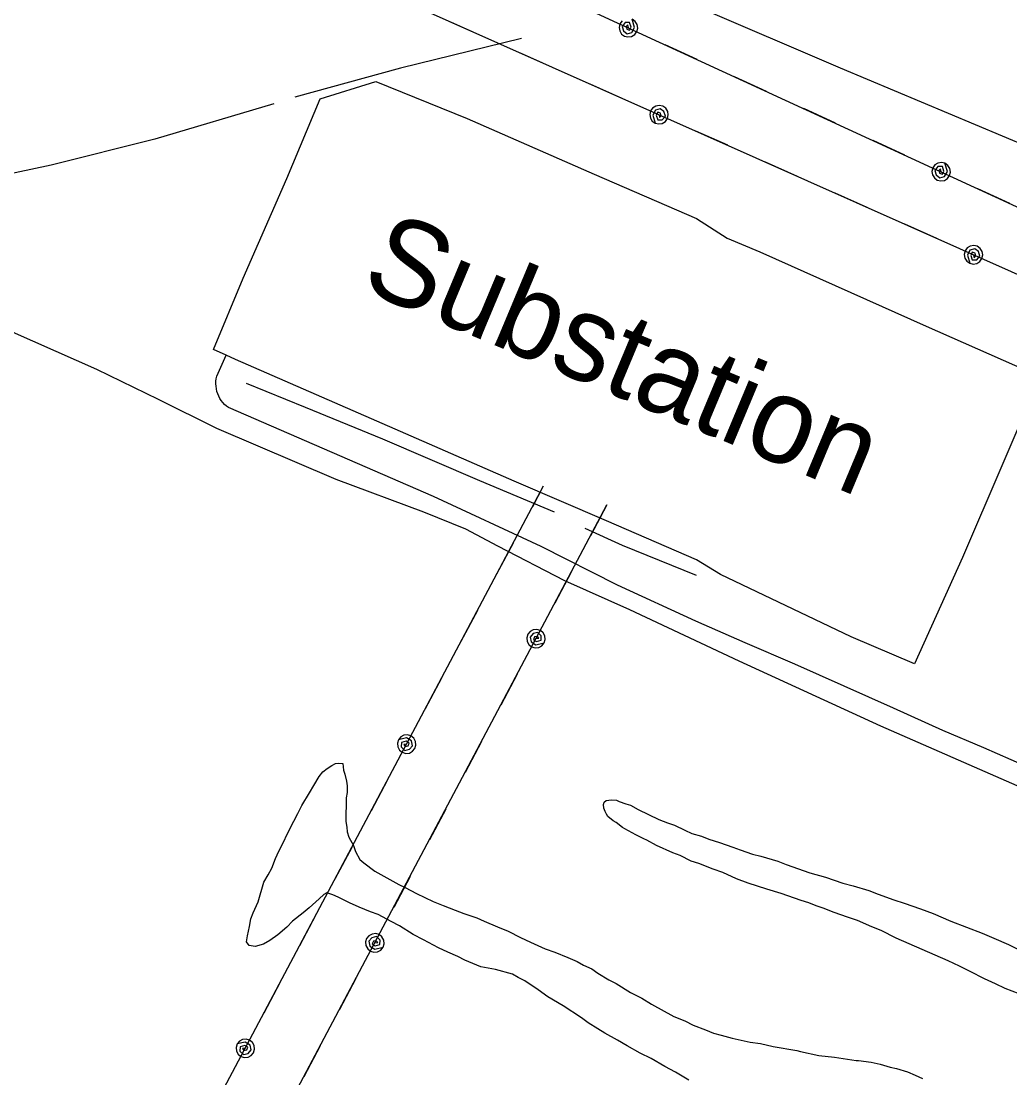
# Model space of a CAD drawing. Extents: x 3297735 to 3335592, y 670436 to 695807.
# Drawn here: x 3305005 to 3305964, y 683651 to 684677 of the extents above; entities that cross this region are included whole.
import ezdxf

# ---------------------------------------------------------------- set-up
doc = ezdxf.new("R2010")
doc.units = 0
for name, color, linetype in [('V-ROAD-CNTR', 7, 'Continuous'), ('V-SITE-OTLN', 7, 'Continuous'), ('V-SITE-OTLN-IDEN', 7, 'Continuous'), ('V-SITE-VEGE', 7, 'Continuous'), ('V-TOPO-SHOR', 7, 'Continuous'), ('V-UTIL-LINE', 7, 'Continuous')]:
    doc.layers.add(name, color=color, linetype=linetype)

msp = doc.modelspace()

# ---------------------------------------------------------------- linework, layer by layer
at = {"layer": 'V-ROAD-CNTR'}
for points in [[(3305206.1, 684301.6), (3305204.1, 684303.1), (3305202.3, 684304.7), (3305200.7, 684306.6), (3305199.2, 684308.5), (3305197.8, 684310.6), (3305196.7, 684312.8), (3305195.7, 684315.1), (3305195, 684317.4), (3305194.4, 684319.8), (3305194.1, 684322.3), (3305193.9, 684324.7), (3305194, 684327.2), (3305194.3, 684329.7), (3305194.8, 684332.1), (3305203.8, 684352.5)], [(3305659.4, 684094.3), (3305583.4, 684129.5), (3305509.6, 684166.8), (3305405, 684215.4), (3305306.6, 684258.2), (3305206.1, 684301.6)], [(3305978.8, 683954.1), (3305939, 683971.4), (3305899.1, 683988.5), (3305851.4, 684010.1), (3305803.5, 684031.4), (3305755.6, 684052.6), (3305707.5, 684073.5), (3305659.4, 684094.3)]]:
    msp.add_lwpolyline(points, dxfattribs=at)
at = {"layer": 'V-SITE-OTLN'}
msp.add_lwpolyline([(3305660.1, 684485), (3305689.9, 684465.9), (3305721.7, 684452.9), (3305883, 684380.7), (3305993.4, 684331.9), (3305918.2, 684156.1), (3305871.7, 684053.2), (3305810.1, 684079.3), (3305683.6, 684139.7), (3305660.1, 684153.9), (3305573, 684191.8), (3305483.3, 684230.4), (3305345, 684290.7), (3305212.9, 684348.4), (3305203.8, 684352.5), (3305191.6, 684358.1), (3305220.5, 684427.1), (3305262.9, 684523.9), (3305295, 684601.2), (3305349.1, 684618), (3305437.7, 684582), (3305561, 684528.2)], close=True, dxfattribs=at)
at = {"layer": 'V-SITE-VEGE'}
for points in [[(3305652.6, 683649.2), (3305639.7, 683657), (3305629.5, 683662.5), (3305616.1, 683670.3), (3305605.4, 683675.4), (3305593, 683682.3), (3305583.6, 683687.8), (3305571.2, 683694.7), (3305564.5, 683698.8), (3305555.1, 683704.7), (3305548.5, 683709.7), (3305530.7, 683721.2), (3305516, 683729.9), (3305506.7, 683736.7), (3305493.8, 683745.4), (3305487.1, 683748.7), (3305481.8, 683751.9), (3305465.2, 683756.6), (3305450.9, 683759), (3305435.3, 683765.5), (3305428.6, 683769.1), (3305418.8, 683773.3), (3305409.9, 683777.5), (3305395.2, 683785.3), (3305385.4, 683790.3), (3305372.1, 683799), (3305364.1, 683803.2), (3305351.2, 683810), (3305344, 683812.4), (3305332.9, 683817), (3305323.5, 683821.2), (3305312.4, 683826.7), (3305307.5, 683829), (3305301.7, 683830.9), (3305298.5, 683829.1), (3305294, 683825.1), (3305284.4, 683816.3), (3305278.6, 683811.4), (3305268.1, 683803.5), (3305262.7, 683797.7), (3305254.1, 683790.2), (3305246.4, 683784.5), (3305240.1, 683781), (3305232, 683778.9), (3305226.1, 683779.8), (3305223.5, 683783.5), (3305224.5, 683789.3), (3305226.4, 683798.2), (3305227.8, 683805.8), (3305230.1, 683811.6), (3305234.8, 683822.3), (3305240.4, 683841.1), (3305244.5, 683848.2), (3305248.2, 683854.9), (3305251.9, 683864.2), (3305255.1, 683871.4), (3305259.7, 683880.7), (3305262.9, 683887), (3305269.4, 683900.3), (3305273.5, 683907.9), (3305277.2, 683915.5), (3305284.6, 683927.9), (3305289.1, 683935), (3305294.2, 683943.9), (3305297.8, 683948.4), (3305301.9, 683951.5), (3305306.4, 683954.5), (3305310, 683956.3), (3305313.2, 683956.7), (3305317.2, 683956.2), (3305317.6, 683949.9), (3305318.9, 683945.9), (3305320.6, 683939.1), (3305321.4, 683934.6), (3305321.3, 683928.3), (3305320.4, 683923)], [(3305320.4, 683923), (3305320.1, 683900.1), (3305320.9, 683894.7), (3305321.3, 683890.2), (3305323, 683884.8), (3305327.4, 683876.7), (3305329.5, 683870.9), (3305333.5, 683863.2), (3305337.5, 683860), (3305348.1, 683851.8), (3305357, 683847.2), (3305371.3, 683838.9), (3305377.5, 683836.2), (3305388.6, 683830.2), (3305396.7, 683826.5), (3305404.7, 683822.4), (3305414.5, 683818.6), (3305426.1, 683814), (3305434.6, 683810.8), (3305447.1, 683806.6), (3305454.2, 683803.3), (3305467.1, 683797.8), (3305477.4, 683793.6), (3305489.4, 683787.6), (3305499.2, 683783), (3305513.5, 683776.6), (3305522.9, 683773.3), (3305535.3, 683768.2), (3305544.3, 683764.1), (3305550.5, 683760.8), (3305558.5, 683757.1), (3305564.3, 683753), (3305575, 683746.6), (3305582.1, 683742.9), (3305596.3, 683734.2), (3305607, 683728.7), (3305616.4, 683722.8), (3305638.2, 683710.8), (3305648.9, 683706.7), (3305656.9, 683702.5), (3305668.9, 683697.9), (3305676.5, 683694.6), (3305684.1, 683692.7), (3305694.8, 683689.9), (3305712.3, 683686.1), (3305722.1, 683684.6), (3305734.6, 683681.8), (3305757.4, 683677.9), (3305761, 683676.9), (3305778.9, 683673.1), (3305794.1, 683671.6), (3305815.2, 683668.2), (3305817.4, 683668.1), (3305829.5, 683666.6), (3305838.4, 683664.7), (3305848.2, 683661.9), (3305854.1, 683660.5), (3305864.8, 683657.2), (3305872.4, 683654), (3305879.5, 683650.8)], [(3305986.7, 683727.8), (3305959.5, 683738), (3305950.2, 683742.6), (3305939.5, 683747.3), (3305925.7, 683754.6), (3305915.4, 683759.7), (3305904.3, 683764.8), (3305853.9, 683786.9), (3305839.2, 683794.3), (3305830.3, 683798), (3305816.5, 683804), (3305806.6, 683807.3), (3305793.7, 683811.9), (3305783, 683816.1), (3305776.3, 683818.4), (3305769.2, 683821.2), (3305761.6, 683823.6), (3305742.4, 683830.1), (3305728.5, 683834.3), (3305710.2, 683840.4), (3305699.1, 683844.5), (3305685.7, 683850.5), (3305676.3, 683853.8), (3305662.5, 683859.4), (3305654.9, 683861.7), (3305644.2, 683867.2), (3305637.1, 683869.6), (3305621.5, 683876.9), (3305612.1, 683882), (3305609, 683883.4), (3305601.4, 683887.1), (3305590.8, 683893), (3305588.5, 683894.4), (3305582.3, 683899), (3305579.2, 683900.8), (3305574.3, 683904.9), (3305573, 683907.1), (3305571.7, 683909.9), (3305570.4, 683913), (3305570, 683916.6), (3305570.5, 683918.8), (3305572.7, 683920.6), (3305577.7, 683921), (3305582.6, 683920.9), (3305585.3, 683919.5), (3305591.5, 683917.2), (3305596, 683915.8), (3305603.6, 683911.7), (3305623.6, 683902), (3305632.1, 683898.8), (3305638.8, 683896.4), (3305649, 683891.8), (3305655.7, 683888.6), (3305665.1, 683885.8), (3305672.2, 683883), (3305682.5, 683879.7), (3305695.4, 683875.1), (3305702.6, 683872.7), (3305714.6, 683868.5), (3305722.7, 683866.6), (3305739.2, 683861.5), (3305747.2, 683858.3), (3305770, 683850.3), (3305785.2, 683846.1), (3305793.7, 683843.3), (3305802.1, 683840.1), (3305812, 683837.7)], [(3305812, 683837.7), (3305827.2, 683833), (3305836.5, 683829.7), (3305851.7, 683824.2), (3305861.5, 683820.9), (3305877.6, 683815.3), (3305889.6, 683810.7), (3305907, 683803.3), (3305937.4, 683791.7), (3305948.5, 683787), (3305962.8, 683780.6), (3305972.6, 683776)]]:
    msp.add_lwpolyline(points, dxfattribs=at)
at = {"layer": 'V-TOPO-SHOR'}
msp.add_line((3305839, 683992.6), (3305701.4, 684055.7), dxfattribs=at)
for points in [[(3306009.5, 684543), (3305799.7, 684631.1), (3305660.1, 684690.9)], [(3305490.4, 684659.8), (3305372.9, 684630.9), (3305270.4, 684602.9)], [(3305250.2, 684596.3), (3305134.8, 684562.1), (3305034, 684537), (3304909.2, 684510.2), (3304804.6, 684483.7), (3304809.3, 684485)], [(3305701.4, 684055.7), (3305595.4, 684105.3), (3305532.5, 684133.7), (3305467.6, 684167.2), (3305436.3, 684183.6), (3305395.5, 684200.1), (3305310.5, 684231.8), (3305194.8, 684281.3), (3305138.4, 684309.6), (3305078.5, 684338.7), (3304976.5, 684383.7), (3304916.4, 684409.8), (3304856.3, 684434.6), (3304791.3, 684460.1)], [(3305522.5, 684200.1), (3305450, 684230.5), (3305355.8, 684271), (3305280.8, 684301.8), (3305223.6, 684325.1)], [(3305660.1, 684138.6), (3305588.5, 684168), (3305552.1, 684184.5)], [(3306341.8, 683773), (3306260.6, 683808.1), (3306123.8, 683866.6), (3305971.4, 683934.6), (3305839, 683992.6)]]:
    msp.add_lwpolyline(points, dxfattribs=at)
at = {"layer": 'V-UTIL-LINE'}
for points in [[(3301855.9, 686290.9), (3302508.1, 686015.9), (3303718.5, 685476.3), (3304541.8, 685139.2), (3305359.1, 684778.4), (3306932, 684054.1), (3307415, 683680.5), (3308058.5, 683385.6), (3308857.4, 683018.6), (3310271.9, 682456)], [(3310256.8, 682384.2), (3308755.9, 682962.6), (3307386.3, 683601.8), (3306906.5, 684014.6), (3304924.5, 684897.2), (3303491.5, 685473.4), (3301855.9, 686171)], [(3305453, 684661.8), (3305421.9, 684675.7)], [(3305588, 684676.8), (3305585.9, 684674), (3305585.1, 684670.5), (3305585.7, 684667.1), (3305587.5, 684664.1), (3305590.3, 684662), (3305593.7, 684661.2), (3305597.2, 684661.8), (3305600.2, 684663.6), (3305602.3, 684666.4), (3305603.1, 684669.8), (3305602.5, 684673.3), (3305600.7, 684676.3), (3305597.9, 684678.4)], [(3305594.1, 684670.2), (3305593.6, 684673), (3305592, 684671.4), (3305592.5, 684668.7), (3305595.3, 684667.8), (3305596.8, 684670.8), (3305595.3, 684675.2), (3305591.1, 684675.2), (3305587.9, 684671.5), (3305589.3, 684667.1), (3305592.9, 684664.4), (3305597.5, 684665.7), (3305600.1, 684670.5), (3305597.9, 684678.4)], [(3305629.5, 684653.9), (3305660.4, 684639.7)], [(3305520.6, 684631.7), (3305489.5, 684645.6)], [(3305696.7, 684622.9), (3305727.6, 684608.7)], [(3305588.2, 684601.6), (3305557.1, 684615.5)], [(3305623.8, 684585.8), (3305624.3, 684583), (3305625.9, 684584.6), (3305625.4, 684587.3), (3305622.6, 684588.2), (3305621, 684585.2), (3305622.6, 684580.7), (3305626.9, 684580.8), (3305630, 684584.5), (3305628.5, 684588.9), (3305625, 684591.6), (3305620.3, 684590.3), (3305617.8, 684585.4), (3305620.1, 684577.6), (3305623.5, 684576.8), (3305627, 684577.4), (3305630, 684579.3), (3305632, 684582.1), (3305632.8, 684585.6), (3305632.2, 684589), (3305630.3, 684592), (3305627.4, 684594), (3305624, 684594.8), (3305620.6, 684594.2), (3305617.6, 684592.3), (3305615.6, 684589.4), (3305614.8, 684586), (3305615.4, 684582.6), (3305617.3, 684579.6), (3305620.1, 684577.6)], [(3305763.9, 684592), (3305794.8, 684577.8)], [(3305690.5, 684556.1), (3305659.4, 684569.9)], [(3305831.2, 684561), (3305862, 684546.8)], [(3305758.1, 684526), (3305727, 684539.8)], [(3305897.5, 684530.5), (3305897, 684533.3), (3305895.3, 684531.7), (3305895.9, 684529), (3305898.7, 684528.1), (3305900.2, 684531.1), (3305898.7, 684535.5), (3305894.4, 684535.5), (3305891.3, 684531.8), (3305892.7, 684527.4), (3305896.2, 684524.7), (3305900.9, 684526), (3305903.5, 684530.8), (3305901.2, 684538.7), (3305897.8, 684539.5), (3305894.4, 684538.9), (3305891.4, 684537.1), (3305889.3, 684534.3), (3305888.5, 684530.8), (3305889, 684527.4), (3305890.9, 684524.4), (3305893.7, 684522.3), (3305897.1, 684521.5), (3305900.6, 684522), (3305903.6, 684523.9), (3305905.7, 684526.7), (3305906.5, 684530.1), (3305905.9, 684533.6), (3305904.1, 684536.6), (3305901.2, 684538.7)], [(3305825.7, 684495.9), (3305794.6, 684509.7)], [(3305932.9, 684514.2), (3305963.8, 684500)], [(3305893.3, 684465.8), (3305862.2, 684479.6)], [(3305928.9, 684449.9), (3305929.4, 684447.1), (3305931.1, 684448.8), (3305930.5, 684451.4), (3305927.7, 684452.3), (3305926.2, 684449.3), (3305927.7, 684444.9), (3305932, 684444.9), (3305935.1, 684448.7), (3305933.7, 684453), (3305930.1, 684455.7), (3305925.4, 684454.4), (3305922.9, 684449.5), (3305925.2, 684441.7), (3305928.7, 684440.9), (3305932.1, 684441.5), (3305935.1, 684443.4), (3305937.1, 684446.3), (3305937.9, 684449.7), (3305937.3, 684453.2), (3305935.4, 684456.1), (3305932.6, 684458.1), (3305929.1, 684458.9), (3305925.7, 684458.3), (3305922.7, 684456.5), (3305920.7, 684453.6), (3305919.9, 684450.2), (3305920.5, 684446.7), (3305922.4, 684443.7), (3305925.2, 684441.7)], [(3301860.2, 678854.6), (3302749.5, 680157.2), (3303450, 681122.8), (3303793.6, 681594.8), (3304457.9, 682546.7), (3304818.3, 683067.2), (3305153.9, 683550.9), (3305511.9, 684225.7)], [(3305501.3, 684205.7), (3305511.9, 684225.7)], [(3301860.2, 678741.7), (3302100.2, 679110.9), (3302802.9, 680133.1), (3303205.2, 680650.4), (3303503.6, 681086.2), (3303865.1, 681573.6), (3304514.5, 682538.1), (3304859.7, 683021.7), (3305210.5, 683522.6), (3305573.3, 684207.4)], [(3305573.3, 684207.4), (3305557.3, 684177.3)], [(3305466.6, 684140.3), (3305482.5, 684170.3)], [(3305538.6, 684142), (3305522.7, 684111.9)], [(3305431.9, 684074.9), (3305447.9, 684105)], [(3305504.4, 684077.5), (3305507.3, 684077.8), (3305505.8, 684079.6), (3305503, 684079.2), (3305502, 684076.4), (3305504.9, 684074.7), (3305509.4, 684076), (3305509.6, 684080.2), (3305506.1, 684083.6), (3305501.7, 684082.4), (3305498.8, 684079), (3305499.7, 684074.3), (3305504.4, 684071.5), (3305512.4, 684073.3), (3305513.4, 684076.6), (3305513.1, 684080.1), (3305511.4, 684083.2), (3305508.7, 684085.4), (3305505.3, 684086.4), (3305501.8, 684086.1), (3305498.7, 684084.4), (3305496.5, 684081.7), (3305495.5, 684078.3), (3305495.8, 684074.8), (3305497.5, 684071.7), (3305500.2, 684069.5), (3305503.6, 684068.5), (3305507.1, 684068.9), (3305510.2, 684070.5), (3305512.4, 684073.3)], [(3305397.2, 684009.6), (3305413.2, 684039.6)], [(3305486.2, 684043), (3305470.3, 684013)], [(3305379, 683975.1), (3305376.1, 683974.8), (3305377.7, 683973), (3305380.4, 683973.4), (3305381.5, 683976.2), (3305378.5, 683977.9), (3305374, 683976.6), (3305373.8, 683972.4), (3305377.3, 683969), (3305381.7, 683970.1), (3305384.6, 683973.5), (3305383.7, 683978.3), (3305379, 683981.1), (3305371, 683979.3), (3305370, 683976), (3305370.4, 683972.5), (3305372, 683969.4), (3305374.8, 683967.2), (3305378.1, 683966.2), (3305381.6, 683966.5), (3305384.7, 683968.2), (3305386.9, 683970.9), (3305387.9, 683974.3), (3305387.6, 683977.8), (3305385.9, 683980.8), (3305383.2, 683983.1), (3305379.8, 683984.1), (3305376.3, 683983.7), (3305373.2, 683982.1), (3305371, 683979.3)], [(3305451.6, 683977.6), (3305435.6, 683947.6)], [(3305344.8, 683910.6), (3305360.7, 683940.7)], [(3305416.9, 683912.2), (3305401, 683882.2)], [(3305310.1, 683845.2), (3305326, 683875.3)], [(3305382.3, 683846.8), (3305366.4, 683816.8)], [(3305275.4, 683779.9), (3305291.3, 683809.9)], [(3305348.1, 683782.3), (3305351, 683782.7), (3305349.4, 683784.4), (3305346.7, 683784), (3305345.6, 683781.3), (3305348.5, 683779.6), (3305353.1, 683780.8), (3305353.3, 683785.1), (3305349.8, 683788.4), (3305345.3, 683787.3), (3305342.4, 683783.9), (3305343.4, 683779.2), (3305348.1, 683776.3), (3305356.1, 683778.1), (3305357.1, 683781.5), (3305356.7, 683785), (3305355, 683788.1), (3305352.3, 683790.3), (3305349, 683791.3), (3305345.5, 683790.9), (3305342.4, 683789.3), (3305340.2, 683786.5), (3305339.1, 683783.2), (3305339.5, 683779.7), (3305341.2, 683776.6), (3305343.9, 683774.4), (3305347.3, 683773.4), (3305350.7, 683773.7), (3305353.8, 683775.4), (3305356.1, 683778.1)], [(3305240.7, 683714.5), (3305256.7, 683744.5)], [(3305329.8, 683747.9), (3305313.9, 683717.8)], [(3305222.5, 683680.1), (3305219.6, 683679.7), (3305221.1, 683678), (3305223.9, 683678.4), (3305224.9, 683681.1), (3305222, 683682.8), (3305217.5, 683681.6), (3305217.3, 683677.3), (3305220.8, 683674), (3305225.2, 683675.1), (3305228.1, 683678.5), (3305227.2, 683683.2), (3305222.5, 683686.1), (3305214.5, 683684.3), (3305213.5, 683680.9), (3305213.8, 683677.4), (3305215.5, 683674.3), (3305218.2, 683672.1), (3305221.6, 683671.1), (3305225.1, 683671.5), (3305228.2, 683673.1), (3305230.4, 683675.8), (3305231.4, 683679.2), (3305231.1, 683682.7), (3305229.4, 683685.8), (3305226.7, 683688), (3305223.3, 683689), (3305219.8, 683688.7), (3305216.7, 683687), (3305214.5, 683684.3)], [(3305295.2, 683682.5), (3305279.3, 683652.4)]]:
    msp.add_lwpolyline(points, dxfattribs=at)

# ---------------------------------------------------------------- texts
at = {"layer": 'V-SITE-OTLN-IDEN'}
msp.add_text('Substation', height=83, rotation=337.2972, dxfattribs=at).set_placement((3305332.3, 684417.4))

doc.saveas('drawing.dxf')
